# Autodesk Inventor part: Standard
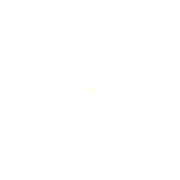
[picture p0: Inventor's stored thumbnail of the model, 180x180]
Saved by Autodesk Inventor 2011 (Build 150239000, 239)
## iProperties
Created: 2005-05
Part Number: Standard
Document SubType Name: Modeling
Designer: JWe
Density: 1 g/cm^3
Author: JWe
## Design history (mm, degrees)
sketch "Sketch1"
  geometry: 1 further point
  constraints: 1 other
